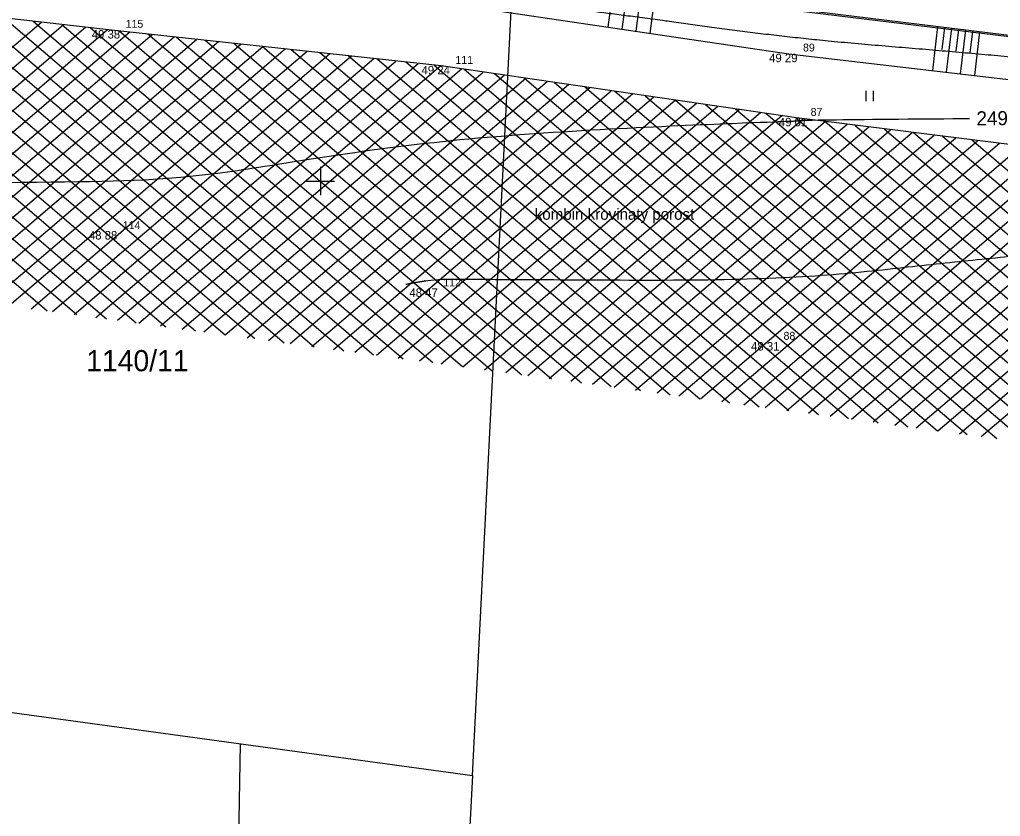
# Model space of a CAD drawing. Extents: x -704057 to -703795, y -1008732 to -1008584.
# Drawn here: x -703910.66 to -703875.92, y -1008697.5 to -1008669.28 of the extents above; entities that cross this region are included whole.
import ezdxf

# ---------------------------------------------------------------- set-up
doc = ezdxf.new("R2010")
doc.units = 0
for name, color, linetype in [('Z_body', 7, 'Continuous'), ('Z_body_cisla', 7, 'Continuous'), ('Z_body_vysky', 7, 'Continuous'), ('Z_hekt_sit', 7, 'Continuous'), ('Z_katastr_cisla_pozemkove', 7, 'Continuous'), ('Z_katastr_hranice', 7, 'Continuous'), ('Z_katastr_vnitrni_kresba', 7, 'Continuous'), ('Z_popis', 7, 'Continuous'), ('Z_teren_hrany_paty', 7, 'Continuous'), ('Z_vrstevnice_popis', 7, 'Continuous'), ('Z_vrstevnice_vedlejsi', 7, 'Continuous'), ('Z_zelen_souvisla', 7, 'Continuous')]:
    doc.layers.add(name, color=color, linetype=linetype)

# ---------------------------------------------------------------- blocks, each defined once
blk = doc.blocks.new('POINT_DISPLAY')
blk.add_line((0, 0), (0, 0))
blk = doc.blocks.new('Z306')
for p, q in [((-0.13, 0.17), (-0.13, -0.2)), ((0.13, 0.17), (0.13, -0.2))]:
    blk.add_line(p, q)

msp = doc.modelspace()

# ---------------------------------------------------------------- linework, layer by layer
at = {"layer": 'Z_hekt_sit'}
for p, q in [((-703900, -1008674.5), (-703900, -1008675.5)), ((-703900.5, -1008675), (-703899.5, -1008675))]:
    msp.add_line(p, q, dxfattribs=at)
at = {"layer": 'Z_katastr_hranice'}
for p, q in [((-703907.73, -1008665.91), (-703871.83, -1008670.35)), ((-703972.28, -1008685.45), (-703894.62, -1008696.05)), ((-703902.91, -1008699.56), (-703902.83, -1008694.93)), ((-703894.62, -1008696.05), (-703894.85, -1008700.61))]:
    msp.add_line(p, q, dxfattribs=at)
at = {"layer": 'Z_katastr_vnitrni_kresba'}
msp.add_line((-703894.62, -1008696.05), (-703893.18, -1008667.71), dxfattribs=at)
at = {"layer": 'Z_teren_hrany_paty'}
for p, q in [((-703889.63, -1008668.11), (-703889.82, -1008669.55)), ((-703889.13, -1008668.17), (-703889.33, -1008669.62)), ((-703888.64, -1008668.23), (-703888.83, -1008669.69)), ((-703888.14, -1008668.3), (-703888.34, -1008669.77)), ((-703895.72, -1008668.68), (-703883.41, -1008670.49)), ((-703871.14, -1008670.4), (-703883.02, -1008668.93)), ((-703878.15, -1008669.53), (-703878.33, -1008671.08)), ((-703877.9, -1008669.56), (-703877.99, -1008670.34)), ((-703877.65, -1008669.59), (-703877.84, -1008671.14)), ((-703877.4, -1008669.63), (-703877.5, -1008670.4)), ((-703877.15, -1008669.66), (-703877.34, -1008671.2)), ((-703876.91, -1008669.69), (-703877, -1008670.46)), ((-703876.66, -1008669.72), (-703876.84, -1008671.26)), ((-703883.41, -1008670.49), (-703871.38, -1008671.9))]:
    msp.add_line(p, q, dxfattribs=at)
at = {"layer": 'Z_vrstevnice_popis'}
msp.add_open_spline([(-703922.315, -1008675.745), (-703920.255, -1008675.133), (-703919.418, -1008675.195), (-703918.102, -1008675.05), (-703907.476, -1008675.061), (-703903.573, -1008674.82), (-703895.854, -1008673.376), (-703883.381, -1008672.872), (-703883.154, -1008672.873), (-703883.026, -1008672.86), (-703882.713, -1008672.828), (-703878.528, -1008672.795), (-703877.019, -1008672.782)], degree=3, dxfattribs=at)
at = {"layer": 'Z_vrstevnice_vedlejsi'}
for points in [[(-703944.218, -1008669.537), (-703942.215, -1008669.847), (-703941.835, -1008669.79), (-703940.983, -1008669.911), (-703940.538, -1008669.059), (-703940.441, -1008669.011), (-703939.659, -1008668.87), (-703938.392, -1008666.573), (-703937.218, -1008665.198), (-703936.994, -1008664.158), (-703936.811, -1008663.182), (-703935.504, -1008662.788), (-703930.851, -1008662.989), (-703930.683, -1008662.945), (-703930.514, -1008662.948), (-703928.53, -1008663.14), (-703926.451, -1008662.869), (-703924.285, -1008662.962), (-703918.453, -1008660.188), (-703917.529, -1008662.583), (-703908.804, -1008661.73), (-703914.417, -1008658.58), (-703914.255, -1008657.775), (-703916.458, -1008657.408), (-703916.075, -1008656.975), (-703916.505, -1008656.883), (-703916.435, -1008655.703), (-703915.746, -1008656.007), (-703915.438, -1008656.225), (-703913.541, -1008656.36), (-703913.202, -1008656.502), (-703907.93, -1008657.256), (-703905.824, -1008657.417), (-703900.033, -1008658.024), (-703894.345, -1008658.848), (-703890.179, -1008659.57), (-703887.702, -1008659.871), (-703882.266, -1008660.175), (-703878.347, -1008660.959), (-703873.149, -1008661.531), (-703869.803, -1008661.293), (-703867.148, -1008661.514), (-703856.66, -1008662.48), (-703848.555, -1008661.935), (-703843.582, -1008661.747), (-703840.018, -1008661.713), (-703835.656, -1008661.182), (-703832.168, -1008661.259), (-703831.497, -1008661.293), (-703819.488, -1008662.346), (-703817.521, -1008662.543), (-703807.841, -1008663.114), (-703805.78, -1008663.132)], [(-703806.645, -1008669.413), (-703810.064, -1008669.091), (-703818.896, -1008668.231), (-703821.949, -1008667.886), (-703832.348, -1008666.911), (-703832.429, -1008666.905), (-703837.82, -1008666.255), (-703832.713, -1008666.908), (-703832.355, -1008666.952), (-703825.705, -1008667.99), (-703819.056, -1008669.026), (-703815.993, -1008669.415), (-703810.462, -1008670.24), (-703806.87, -1008671.09), (-703808.766, -1008673.591), (-703809.75, -1008673.886), (-703817.454, -1008673.52), (-703819.628, -1008673.248), (-703826.836, -1008673.24), (-703833.27, -1008673.353), (-703835.286, -1008673.278), (-703844.44, -1008672.81), (-703850.152, -1008672.821), (-703855.806, -1008672.275), (-703857.13, -1008672.165), (-703860.162, -1008671.947), (-703871.237, -1008671.005), (-703876.973, -1008670.473), (-703883.276, -1008669.953), (-703888.652, -1008669.207), (-703892.007, -1008668.787), (-703895.701, -1008668.459), (-703900.931, -1008667.965), (-703907.22, -1008668.487), (-703913.351, -1008668.979), (-703918.495, -1008669.549), (-703927.701, -1008668.863), (-703930.6, -1008669.724), (-703932.124, -1008670.909), (-703936.972, -1008673.376)], [(-703896.98, -1008678.651), (-703896.133, -1008678.493), (-703895.427, -1008678.464), (-703883.839, -1008678.545), (-703877.35, -1008677.837), (-703872.416, -1008677.342), (-703866.301, -1008677.05), (-703856.707, -1008676.518), (-703852.893, -1008676.277), (-703845.162, -1008676.191), (-703841.604, -1008676.353), (-703835.881, -1008677.017), (-703835.026, -1008677.731), (-703834.61, -1008677.894), (-703834.308, -1008677.982), (-703834.186, -1008677.892), (-703833.394, -1008677.301), (-703832.871, -1008677.385), (-703832.441, -1008677.368), (-703830.672, -1008676.925), (-703824.679, -1008677.145), (-703820.88, -1008677.475), (-703818.446, -1008678.206), (-703817.605, -1008678.327), (-703817.159, -1008678.382), (-703815.634, -1008679.383), (-703815.241, -1008679.772), (-703814.913, -1008679.988), (-703810.519, -1008681.242), (-703809.363, -1008681.548)]]:
    msp.add_open_spline(points, degree=2, dxfattribs=at)
at = {"layer": 'Z_zelen_souvisla'}
for p, q in [((-703923.78, -1008667.55), (-703909.68, -1008679.59)), ((-703922.7, -1008667.72), (-703908.63, -1008679.73)), ((-703921.61, -1008667.9), (-703907.58, -1008679.88)), ((-703920.52, -1008668.07), (-703906.53, -1008680.02)), ((-703919.43, -1008668.24), (-703905.48, -1008680.16)), ((-703918.35, -1008668.41), (-703904.43, -1008680.3)), ((-703907.4, -1008669.65), (-703918.31, -1008668.42)), ((-703917.32, -1008668.53), (-703903.38, -1008680.44)), ((-703916.3, -1008668.65), (-703902.33, -1008680.58)), ((-703915.28, -1008668.76), (-703901.28, -1008680.73)), ((-703914.26, -1008668.88), (-703900.22, -1008680.87)), ((-703913.24, -1008668.99), (-703899.17, -1008681.01)), ((-703912.22, -1008669.11), (-703898.12, -1008681.15)), ((-703911.2, -1008669.22), (-703897.07, -1008681.29)), ((-703920.19, -1008678.18), (-703909.88, -1008669.37)), ((-703919.43, -1008678.28), (-703909.1, -1008669.46)), ((-703918.66, -1008678.38), (-703908.32, -1008669.55)), ((-703917.9, -1008678.49), (-703907.54, -1008669.63)), ((-703910.18, -1008669.34), (-703896.02, -1008681.43)), ((-703909.16, -1008669.45), (-703894.97, -1008681.57)), ((-703908.14, -1008669.57), (-703893.92, -1008681.72)), ((-703895.72, -1008670.92), (-703907.4, -1008669.65)), ((-703917.13, -1008678.59), (-703906.75, -1008669.72)), ((-703916.37, -1008678.69), (-703905.96, -1008669.81)), ((-703915.6, -1008678.8), (-703905.18, -1008669.89)), ((-703914.84, -1008678.9), (-703904.39, -1008669.98)), ((-703907.13, -1008669.68), (-703892.87, -1008681.86)), ((-703906.11, -1008669.79), (-703891.82, -1008682)), ((-703905.1, -1008669.9), (-703890.76, -1008682.14)), ((-703904.08, -1008670.01), (-703889.71, -1008682.28)), ((-703914.08, -1008679), (-703903.61, -1008670.06)), ((-703913.31, -1008679.1), (-703902.82, -1008670.15)), ((-703912.55, -1008679.21), (-703902.04, -1008670.23)), ((-703911.78, -1008679.31), (-703901.25, -1008670.32)), ((-703903.07, -1008670.12), (-703888.66, -1008682.42)), ((-703902.05, -1008670.23), (-703887.61, -1008682.57)), ((-703901.04, -1008670.34), (-703886.56, -1008682.71)), ((-703911.02, -1008679.41), (-703900.47, -1008670.4)), ((-703910.25, -1008679.52), (-703899.68, -1008670.49)), ((-703909.49, -1008679.62), (-703898.9, -1008670.57)), ((-703908.72, -1008679.72), (-703898.11, -1008670.66)), ((-703900.02, -1008670.45), (-703885.51, -1008682.85)), ((-703899.01, -1008670.56), (-703884.46, -1008682.99)), ((-703897.99, -1008670.67), (-703883.41, -1008683.13)), ((-703907.96, -1008679.83), (-703897.33, -1008670.75)), ((-703907.19, -1008679.93), (-703896.54, -1008670.83)), ((-703906.43, -1008680.03), (-703895.75, -1008670.92)), ((-703905.66, -1008680.13), (-703895, -1008671.03)), ((-703896.98, -1008670.78), (-703882.36, -1008683.27)), ((-703895.97, -1008670.89), (-703881.3, -1008683.41)), ((-703883.14, -1008672.76), (-703895.72, -1008670.92)), ((-703894.91, -1008671.04), (-703880.25, -1008683.56)), ((-703904.9, -1008680.24), (-703894.24, -1008671.14)), ((-703904.13, -1008680.34), (-703893.49, -1008671.25)), ((-703903.37, -1008680.44), (-703892.73, -1008671.36)), ((-703893.84, -1008671.19), (-703879.2, -1008683.7)), ((-703892.77, -1008671.35), (-703878.15, -1008683.84)), ((-703902.6, -1008680.55), (-703891.97, -1008671.47)), ((-703901.84, -1008680.65), (-703891.22, -1008671.58)), ((-703901.07, -1008680.75), (-703890.46, -1008671.69)), ((-703891.71, -1008671.51), (-703877.1, -1008683.98)), ((-703890.64, -1008671.66), (-703876.05, -1008684.12)), ((-703900.31, -1008680.86), (-703889.71, -1008671.8)), ((-703899.54, -1008680.96), (-703888.95, -1008671.91)), ((-703898.78, -1008681.06), (-703888.19, -1008672.02)), ((-703889.57, -1008671.82), (-703875, -1008684.26)), ((-703888.5, -1008671.98), (-703873.95, -1008684.41)), ((-703898.01, -1008681.16), (-703887.44, -1008672.13)), ((-703897.25, -1008681.27), (-703886.68, -1008672.24)), ((-703896.49, -1008681.37), (-703885.93, -1008672.35)), ((-703887.43, -1008672.13), (-703872.9, -1008684.55)), ((-703886.36, -1008672.29), (-703871.84, -1008684.69)), ((-703885.3, -1008672.44), (-703870.79, -1008684.83)), ((-703895.72, -1008681.47), (-703885.17, -1008672.46)), ((-703894.96, -1008681.58), (-703884.41, -1008672.57)), ((-703894.19, -1008681.68), (-703883.66, -1008672.68)), ((-703893.43, -1008681.78), (-703882.9, -1008672.79)), ((-703884.23, -1008672.6), (-703869.74, -1008684.97)), ((-703883.16, -1008672.76), (-703868.69, -1008685.11)), ((-703871.86, -1008674.18), (-703883.14, -1008672.76)), ((-703892.66, -1008681.89), (-703882.13, -1008672.89)), ((-703891.9, -1008681.99), (-703881.35, -1008672.98)), ((-703891.13, -1008682.09), (-703880.58, -1008673.08)), ((-703882.12, -1008672.89), (-703867.64, -1008685.26)), ((-703881.08, -1008673.02), (-703866.59, -1008685.4)), ((-703890.37, -1008682.19), (-703879.81, -1008673.18)), ((-703889.6, -1008682.3), (-703879.04, -1008673.28)), ((-703888.84, -1008682.4), (-703878.27, -1008673.37)), ((-703888.07, -1008682.5), (-703877.5, -1008673.47)), ((-703880.04, -1008673.15), (-703865.54, -1008685.54)), ((-703879, -1008673.28), (-703864.49, -1008685.68)), ((-703877.97, -1008673.41), (-703863.44, -1008685.82)), ((-703887.31, -1008682.61), (-703876.73, -1008673.57)), ((-703886.54, -1008682.71), (-703875.95, -1008673.66)), ((-703885.78, -1008682.81), (-703875.18, -1008673.76)), ((-703876.93, -1008673.54), (-703862.09, -1008686.21)), ((-703885.01, -1008682.92), (-703874.41, -1008673.86)), ((-703884.25, -1008683.02), (-703873.64, -1008673.96)), ((-703883.48, -1008683.12), (-703872.87, -1008674.05)), ((-703882.72, -1008683.22), (-703872.1, -1008674.15)), ((-703881.95, -1008683.33), (-703871.32, -1008674.24)), ((-703881.19, -1008683.43), (-703870.54, -1008674.33)), ((-703880.43, -1008683.53), (-703869.76, -1008674.43)), ((-703879.66, -1008683.64), (-703868.98, -1008674.52)), ((-703878.9, -1008683.74), (-703868.2, -1008674.61)), ((-703878.13, -1008683.84), (-703867.42, -1008674.7)), ((-703877.37, -1008683.95), (-703866.65, -1008674.79)), ((-703876.6, -1008684.05), (-703865.87, -1008674.88))]:
    msp.add_line(p, q, dxfattribs=at)

# ---------------------------------------------------------------- block references
at = {"layer": 'Z_body'}
for p in [(-703907.4, -1008669.65), (-703883.41, -1008670.49), (-703895.72, -1008670.92), (-703883.14, -1008672.76), (-703907.5, -1008676.77), (-703896.15, -1008678.8), (-703884.1, -1008680.7)]:
    msp.add_blockref('POINT_DISPLAY', p, dxfattribs=at)
at = {"layer": 'Z_popis'}
msp.add_blockref('Z306', (-703880.55, -1008671.97), dxfattribs=at)

# ---------------------------------------------------------------- texts
at = {"layer": 'Z_body_cisla'}
for s, p in [('115', (-703906.9, -1008669.57)), ('89', (-703882.91, -1008670.41)), ('111', (-703895.22, -1008670.85)), ('87', (-703882.64, -1008672.69)), ('114', (-703907, -1008676.7)), ('112', (-703895.65, -1008678.73)), ('88', (-703883.6, -1008680.62))]:
    msp.add_text(s, height=0.28, dxfattribs=at).set_placement(p)
at = {"layer": 'Z_body_vysky'}
for s, p in [('49 38', (-703908.1, -1008669.95)), ('49 29', (-703884.11, -1008670.79)), ('49 24', (-703896.42, -1008671.22)), ('49 01', (-703883.765, -1008673.06)), ('48 88', (-703908.2, -1008677.07)), ('48 47', (-703896.85, -1008679.1)), ('48 31', (-703884.75, -1008681))]:
    msp.add_text(s, height=0.3, dxfattribs=at).set_placement(p)
at = {"layer": 'Z_katastr_cisla_pozemkove'}
msp.add_text('1140/11', height=0.75, dxfattribs=at).set_placement((-703908.297, -1008681.735))
at = {"layer": 'Z_popis'}
msp.add_text('kombin.krovinaty porost', height=0.4, dxfattribs=at).set_placement((-703892.41, -1008676.37))
at = {"layer": 'Z_vrstevnice_popis'}
msp.add_text('249', height=0.5, rotation=0.5232, dxfattribs=at).set_placement((-703876.766, -1008673.03))

doc.saveas('drawing.dxf')
